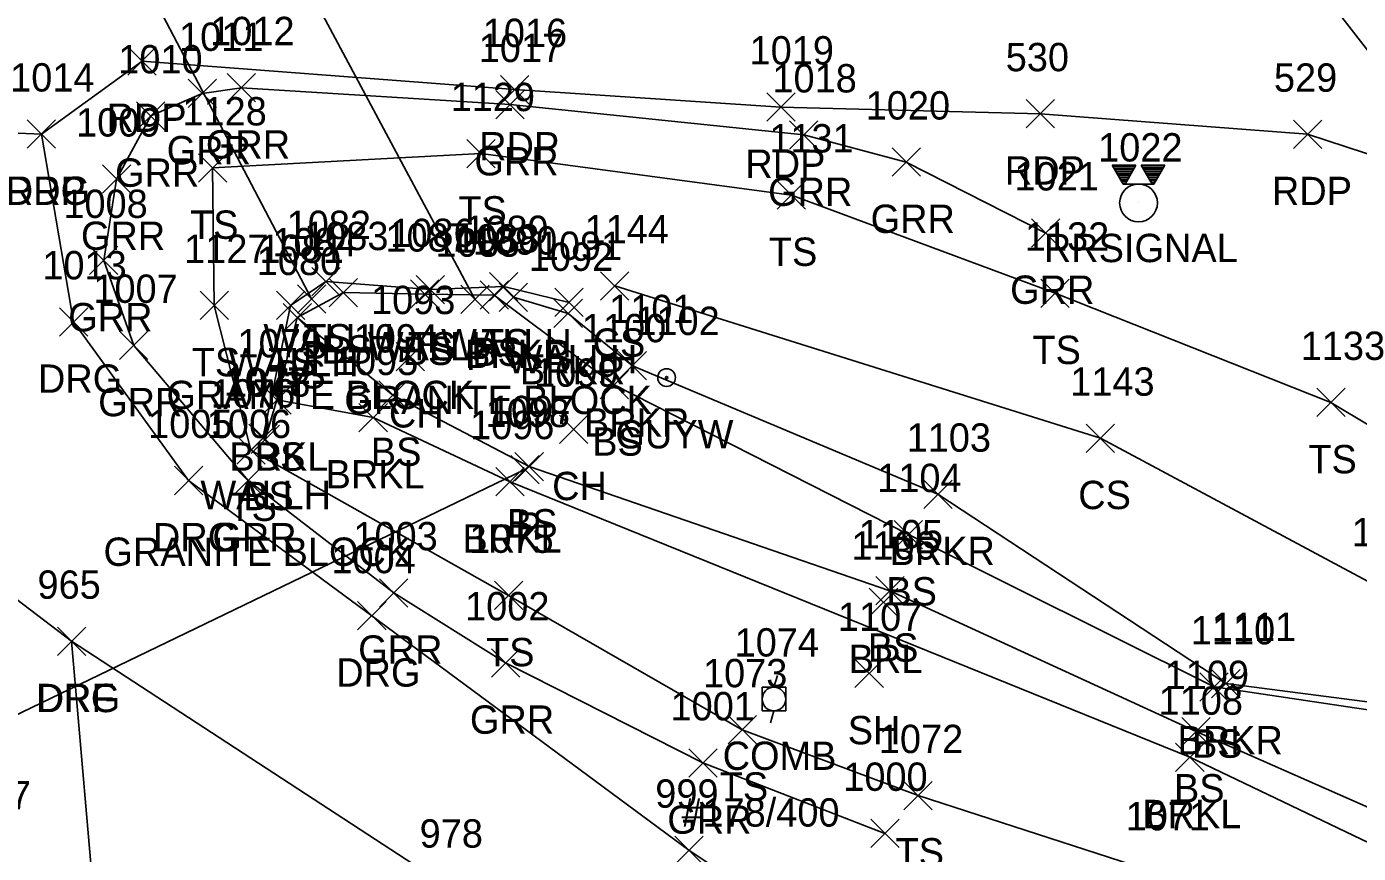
# Model space of a CAD drawing. Extents: x 1679360 to 1685861, y 903420 to 905946.
# Drawn here: x 1679736.4 to 1679830.3, y 903963.9 to 904022.2 of the extents above; entities that cross this region are included whole.
import ezdxf

# ---------------------------------------------------------------- set-up
doc = ezdxf.new("R2010")
doc.units = 0
for name, color, linetype in [('D_A', 7, 'Continuous'), ('D_C', 7, 'Continuous'), ('D_I', 7, 'Continuous'), ('D_TIC', 7, 'Continuous'), ('DCP', 7, 'Continuous'), ('DHW', 7, 'Continuous'), ('L_A', 7, 'Continuous'), ('L_I', 7, 'Continuous'), ('L_TIC', 7, 'Continuous'), ('LAWE', 7, 'Continuous'), ('LELB', 7, 'Continuous'), ('P_A', 7, 'Continuous'), ('P_I', 7, 'Continuous'), ('P_TIC', 7, 'Continuous'), ('PET', 7, 'Continuous'), ('R_A', 7, 'Continuous'), ('R_I', 7, 'Continuous'), ('R_TIC', 7, 'Continuous'), ('RDF', 7, 'Continuous'), ('RDG', 7, 'Continuous'), ('RGR', 7, 'Continuous'), ('RR', 7, 'Continuous'), ('TCSH', 7, 'Continuous'), ('U_A', 7, 'Continuous'), ('U_C', 7, 'Continuous'), ('U_I', 7, 'Continuous'), ('UP', 7, 'Continuous'), ('UPGW', 7, 'Continuous')]:
    doc.layers.add(name, color=color, linetype=linetype)

msp = doc.modelspace()

# ---------------------------------------------------------------- linework, layer by layer
at = {"layer": 'D_TIC'}
for points in [[(1679756.54, 904003.217), (1679758.54, 904005.217)], [(1679758.54, 904003.217), (1679756.54, 904005.217)], [(1679769.077, 904002.866), (1679771.077, 904004.866)], [(1679771.077, 904002.866), (1679769.077, 904004.866)], [(1679755.528, 904001.994), (1679757.528, 904003.994)], [(1679757.528, 904001.994), (1679755.528, 904003.994)], [(1679763.901, 904002.649), (1679765.901, 904004.649)], [(1679765.901, 904002.649), (1679763.901, 904004.649)], [(1679767.043, 904001.965), (1679769.043, 904003.965)], [(1679769.043, 904001.965), (1679767.043, 904003.965)], [(1679754.05, 904001.532), (1679756.05, 904003.532)], [(1679756.05, 904001.532), (1679754.05, 904003.532)], [(1679773.691, 904001.741), (1679775.691, 904003.741)], [(1679775.691, 904001.741), (1679773.691, 904003.741)], [(1679752.098, 903992.157), (1679754.098, 903994.157)], [(1679754.098, 903992.157), (1679752.098, 903994.157)], [(1679770.568, 903989.946), (1679772.568, 903991.946)], [(1679772.568, 903989.946), (1679770.568, 903991.946)]]:
    msp.add_lwpolyline(points, dxfattribs=at)
at = {"layer": 'DCP'}
for points in [[(1679722.806, 904067.249), (1679756.528, 904002.994)], [(1679733.684, 904067.194), (1679768.043, 904002.965)], [(1679729.232, 903970.53), (1679771.568, 903990.946)]]:
    msp.add_lwpolyline(points, dxfattribs=at)
at = {"layer": 'DHW'}
for points in [[(1679757.54, 904004.217), (1679764.901, 904003.649)], [(1679770.077, 904003.866), (1679774.691, 904002.741)], [(1679753.098, 903993.157), (1679755.05, 904002.532)]]:
    msp.add_lwpolyline(points, dxfattribs=at)
at = {"layer": 'L_TIC'}
for points in [[(1679767.469, 904012.239), (1679769.469, 904014.239)], [(1679769.469, 904012.239), (1679767.469, 904014.239)], [(1679748.546, 904011.229), (1679750.546, 904013.229)], [(1679750.546, 904011.229), (1679748.546, 904013.229)], [(1679789.366, 904009.321), (1679791.366, 904011.321)], [(1679791.366, 904009.321), (1679789.366, 904011.321)], [(1679756.54, 904003.217), (1679758.54, 904005.217)], [(1679758.54, 904003.217), (1679756.54, 904005.217)], [(1679769.077, 904002.866), (1679771.077, 904004.866)], [(1679771.077, 904002.866), (1679769.077, 904004.866)], [(1679776.904, 904002.912), (1679778.904, 904004.912)], [(1679778.904, 904002.912), (1679776.904, 904004.912)], [(1679757.772, 904002.433), (1679759.772, 904004.433)], [(1679759.772, 904002.433), (1679757.772, 904004.433)], [(1679763.509, 904002.328), (1679765.509, 904004.328)], [(1679765.509, 904002.328), (1679763.509, 904004.328)], [(1679763.901, 904002.649), (1679765.901, 904004.649)], [(1679765.901, 904002.649), (1679763.901, 904004.649)], [(1679768.411, 904002.26), (1679770.411, 904004.26)], [(1679770.411, 904002.26), (1679768.411, 904004.26)], [(1679769.758, 904002.113), (1679771.758, 904004.113)], [(1679771.758, 904002.113), (1679769.758, 904004.113)], [(1679807.954, 904002.393), (1679809.954, 904004.393)], [(1679809.954, 904002.393), (1679807.954, 904004.393)], [(1679748.667, 904001.531), (1679750.667, 904003.531)], [(1679750.667, 904001.531), (1679748.667, 904003.531)], [(1679754.05, 904001.532), (1679756.05, 904003.532)], [(1679756.05, 904001.532), (1679754.05, 904003.532)], [(1679773.622, 904000.969), (1679775.622, 904002.969)], [(1679775.622, 904000.969), (1679773.622, 904002.969)], [(1679754.517, 904000.673), (1679756.517, 904002.673)], [(1679756.517, 904000.673), (1679754.517, 904002.673)], [(1679754.517, 904000.673), (1679756.517, 904002.673)], [(1679756.517, 904000.673), (1679754.517, 904002.673)], [(1679762.491, 903997.919), (1679764.491, 903999.919)], [(1679764.491, 903997.919), (1679762.491, 903999.919)], [(1679778.149, 903997.281), (1679780.149, 903999.281)], [(1679780.149, 903997.281), (1679778.149, 903999.281)], [(1679776.875, 903995.933), (1679778.875, 903997.933)], [(1679778.875, 903995.933), (1679776.875, 903997.933)], [(1679753.084, 903994.867), (1679755.084, 903996.867)], [(1679755.084, 903994.867), (1679753.084, 903996.867)], [(1679753.084, 903994.867), (1679755.084, 903996.867)], [(1679755.084, 903994.867), (1679753.084, 903996.867)], [(1679761.265, 903995.209), (1679763.265, 903997.209)], [(1679763.265, 903995.209), (1679761.265, 903997.209)], [(1679827.407, 903994.686), (1679829.407, 903996.686)], [(1679829.407, 903994.686), (1679827.407, 903996.686)], [(1679759.871, 903993.62), (1679761.871, 903995.62)], [(1679761.871, 903993.62), (1679759.871, 903995.62)], [(1679774.004, 903992.793), (1679776.004, 903994.793)], [(1679776.004, 903992.793), (1679774.004, 903994.793)], [(1679752.265, 903992.087), (1679754.265, 903994.087)], [(1679754.265, 903992.087), (1679752.265, 903994.087)], [(1679811.152, 903992.161), (1679813.152, 903994.161)], [(1679813.152, 903992.161), (1679811.152, 903994.161)], [(1679751.253, 903991.328), (1679753.253, 903993.328)], [(1679753.253, 903991.328), (1679751.253, 903993.328)], [(1679770.871, 903990.159), (1679772.871, 903992.159)], [(1679772.871, 903990.159), (1679770.871, 903992.159)], [(1679769.523, 903989.096), (1679771.523, 903991.096)], [(1679771.523, 903989.096), (1679769.523, 903991.096)], [(1679799.693, 903988.211), (1679801.693, 903990.211)], [(1679801.693, 903988.211), (1679799.693, 903990.211)], [(1679797.619, 903985.362), (1679799.619, 903987.362)], [(1679799.619, 903985.362), (1679797.619, 903987.362)], [(1679796.314, 903981.397), (1679798.314, 903983.397)], [(1679798.314, 903981.397), (1679796.314, 903983.397)], [(1679769.418, 903981.075), (1679771.418, 903983.075)], [(1679771.418, 903981.075), (1679769.418, 903983.075)], [(1679795.86, 903980.596), (1679797.86, 903982.596)], [(1679797.86, 903980.596), (1679795.86, 903982.596)], [(1679794.849, 903975.571), (1679796.849, 903977.571)], [(1679796.849, 903975.571), (1679794.849, 903977.571)], [(1679820, 903974.857), (1679822, 903976.857)], [(1679822, 903974.857), (1679820, 903976.857)], [(1679819.173, 903974.618), (1679821.173, 903976.618)], [(1679821.173, 903974.618), (1679819.173, 903976.618)], [(1679785.9, 903971.592), (1679787.9, 903973.592)], [(1679787.9, 903971.592), (1679785.9, 903973.592)], [(1679817.901, 903971.468), (1679819.901, 903973.468)], [(1679819.901, 903971.468), (1679817.901, 903973.468)], [(1679817.461, 903969.652), (1679819.461, 903971.652)], [(1679819.461, 903969.652), (1679817.461, 903971.652)], [(1679798.3, 903966.949), (1679800.3, 903968.949)], [(1679800.3, 903966.949), (1679798.3, 903968.949)]]:
    msp.add_lwpolyline(points, dxfattribs=at)
at = {"layer": 'LAWE'}
for points in [[(1679770.758, 904003.113), (1679774.622, 904001.969), (1679779.149, 903998.281), (1679800.693, 903989.211), (1679821, 903975.857), (1679836.965, 903973.787), (1679846.91, 903974.341), (1679851.31, 903976.645)], [(1679754.084, 903995.867), (1679760.871, 903994.62), (1679770.523, 903990.096), (1679818.461, 903970.652), (1679836.034, 903962.252), (1679850.756, 903964.941), (1679856.581, 903970.528)]]:
    msp.add_lwpolyline(points, dxfattribs=at)
at = {"layer": 'LELB'}
for points in [[(1679826.909, 903946.775), (1679816.139, 903962.498), (1679799.3, 903967.949), (1679786.9, 903972.592), (1679770.418, 903982.075), (1679752.253, 903992.328), (1679749.667, 904002.531), (1679749.546, 904012.229), (1679768.469, 904013.239), (1679790.366, 904010.321), (1679808.954, 904003.393), (1679828.407, 903995.686), (1679842.28, 903987.378), (1679854.89, 903981.602), (1679861.766, 903973.84), (1679868.316, 903960.054)], [(1679755.05, 904002.532), (1679757.54, 904004.217)], [(1679846.701, 903976.921), (1679832.005, 903982.539), (1679812.152, 903993.161), (1679777.904, 904003.912)], [(1679753.265, 903993.087), (1679754.084, 903995.867), (1679755.517, 904001.673), (1679758.772, 904003.433), (1679764.509, 904003.328), (1679769.411, 904003.26), (1679777.875, 903996.933), (1679798.619, 903986.362), (1679820.173, 903975.618), (1679837.139, 903973.094), (1679847.38, 903972.765), (1679851.382, 903976.558)], [(1679764.901, 904003.649), (1679770.077, 904003.866)], [(1679755.517, 904001.673), (1679762.265, 903996.209), (1679771.871, 903991.159), (1679797.314, 903982.397), (1679818.901, 903972.468), (1679836.645, 903964.65), (1679849.36, 903967.246), (1679856.205, 903970.751)]]:
    msp.add_lwpolyline(points, dxfattribs=at)
at = {"layer": 'P_TIC'}
for points in [[(1679743.579, 904018.774), (1679745.579, 904020.774)], [(1679745.579, 904018.774), (1679743.579, 904020.774)], [(1679769.859, 904016.762), (1679771.859, 904018.762)], [(1679771.859, 904016.762), (1679769.859, 904018.762)], [(1679788.628, 904015.53), (1679790.628, 904017.53)], [(1679790.628, 904015.53), (1679788.628, 904017.53)], [(1679788.628, 904015.53), (1679790.628, 904017.53)], [(1679790.628, 904015.53), (1679788.628, 904017.53)], [(1679806.928, 904015.053), (1679808.928, 904017.053)], [(1679808.928, 904015.053), (1679806.928, 904017.053)], [(1679736.475, 904013.621), (1679738.475, 904015.621)], [(1679738.475, 904013.621), (1679736.475, 904015.621)], [(1679825.762, 904013.608), (1679827.762, 904015.608)], [(1679827.762, 904013.608), (1679825.762, 904015.608)]]:
    msp.add_lwpolyline(points, dxfattribs=at)
at = {"layer": 'PET'}
for points in [[(1679464.445, 904041.772), (1679494.847, 904039.777), (1679533.658, 904036.864), (1679564.761, 904034.751), (1679595.94, 904030.795), (1679627.793, 904028.133), (1679661.16, 904024.917), (1679697.205, 904019.689), (1679719.417, 904015.397), (1679737.475, 904014.621), (1679744.579, 904019.774), (1679770.859, 904017.762), (1679789.628, 904016.53)], [(1680207.925, 903985.129), (1680151.693, 903989.51), (1680097.956, 903992.814), (1680047.952, 903996.664), (1679996.841, 904001.699), (1679939.177, 904006.29), (1679891.591, 904009.092), (1679852.589, 904011.923), (1679848.664, 904011.26), (1679842.11, 904010.48), (1679836.311, 904011.491), (1679826.762, 904014.608), (1679807.928, 904016.053), (1679789.628, 904016.53)]]:
    msp.add_lwpolyline(points, dxfattribs=at)
at = {"layer": 'R_TIC'}
for points in [[(1679747.822, 904016.487), (1679749.822, 904018.487)], [(1679749.822, 904016.487), (1679747.822, 904018.487)], [(1679750.584, 904016.893), (1679752.584, 904018.893)], [(1679752.584, 904016.893), (1679750.584, 904018.893)], [(1679769.522, 904015.702), (1679771.522, 904017.702)], [(1679771.522, 904015.702), (1679769.522, 904017.702)], [(1679744.181, 904014.902), (1679746.181, 904016.902)], [(1679746.181, 904014.902), (1679744.181, 904016.902)], [(1679736.475, 904013.621), (1679738.475, 904015.621)], [(1679738.475, 904013.621), (1679736.475, 904015.621)], [(1679790.232, 904013.556), (1679792.232, 904015.556)], [(1679792.232, 904013.556), (1679790.232, 904015.556)], [(1679797.462, 904011.646), (1679799.462, 904013.646)], [(1679799.462, 904011.646), (1679797.462, 904013.646)], [(1679741.775, 904010.445), (1679743.775, 904012.445)], [(1679743.775, 904010.445), (1679741.775, 904012.445)], [(1679807.299, 904006.641), (1679809.299, 904008.641)], [(1679809.299, 904006.641), (1679807.299, 904008.641)], [(1679740.875, 904004.703), (1679742.875, 904006.703)], [(1679742.875, 904004.703), (1679740.875, 904006.703)], [(1679738.743, 904000.37), (1679740.743, 904002.37)], [(1679740.743, 904000.37), (1679738.743, 904002.37)], [(1679742.99, 903998.712), (1679744.99, 904000.712)], [(1679744.99, 903998.712), (1679742.99, 904000.712)], [(1679746.854, 903989.18), (1679748.854, 903991.18)], [(1679748.854, 903989.18), (1679746.854, 903991.18)], [(1679751.045, 903989.179), (1679753.045, 903991.179)], [(1679753.045, 903989.179), (1679751.045, 903991.179)], [(1679761.326, 903981.253), (1679763.326, 903983.253)], [(1679763.326, 903981.253), (1679761.326, 903983.253)], [(1679759.777, 903979.639), (1679761.777, 903981.639)], [(1679761.777, 903979.639), (1679759.777, 903981.639)], [(1679738.608, 903977.837), (1679740.608, 903979.837)], [(1679740.608, 903977.837), (1679738.608, 903979.837)], [(1679738.608, 903977.837), (1679740.608, 903979.837)], [(1679740.608, 903977.837), (1679738.608, 903979.837)], [(1679769.205, 903976.312), (1679771.205, 903978.312)], [(1679771.205, 903976.312), (1679769.205, 903978.312)], [(1679783.124, 903969.258), (1679785.124, 903971.258)], [(1679785.124, 903969.258), (1679783.124, 903971.258)], [(1679795.959, 903964.284), (1679797.959, 903966.284)], [(1679797.959, 903964.284), (1679795.959, 903966.284)], [(1679782.134, 903963.096), (1679784.134, 903965.096)], [(1679784.134, 903963.096), (1679782.134, 903965.096)]]:
    msp.add_lwpolyline(points, dxfattribs=at)
at = {"layer": 'RDF'}
msp.add_lwpolyline([(1679739.608, 903978.837), (1679741.406, 903958.01), (1679740.349, 903940.875)], dxfattribs=at)
at = {"layer": 'RDG'}
for points in [[(1679661.16, 904024.917), (1679683.887, 904015.944), (1679697.931, 904008.669), (1679719.81, 903993.908), (1679739.608, 903978.837), (1679766.509, 903961.278), (1679785.717, 903950.364), (1679809.974, 903931.781)], [(1679817.493, 903938.584), (1679800, 903952.789), (1679783.134, 903964.096), (1679760.777, 903980.639), (1679747.854, 903990.18), (1679739.743, 904001.37), (1679737.475, 904014.621)]]:
    msp.add_lwpolyline(points, dxfattribs=at)
at = {"layer": 'RGR'}
msp.add_lwpolyline([(1679796.959, 903965.284), (1679784.124, 903970.258), (1679770.205, 903977.312), (1679762.326, 903982.253), (1679752.045, 903990.179), (1679743.99, 903999.712), (1679741.875, 904005.703), (1679742.775, 904011.445), (1679745.181, 904015.902), (1679748.822, 904017.487), (1679751.584, 904017.893), (1679770.522, 904016.702), (1679791.232, 904014.556), (1679798.462, 904012.646), (1679808.299, 904007.641)], dxfattribs=at)
at = {"layer": 'RR'}
msp.add_lwpolyline([(1679824.636, 904028.723), (1679837.335, 904012.385), (1679861.93, 903982.575), (1679878.201, 903963.702), (1679892.43, 903947.813), (1679907.949, 903930.191), (1679922.381, 903914.406), (1679937.847, 903897.677), (1679952.054, 903882.523), (1679968.97, 903864.985), (1679984.514, 903848.778), (1680002.835, 903830.071), (1680018.619, 903814.033), (1680033.052, 903799.461), (1680047.501, 903784.671), (1680062.832, 903769.48), (1680079.575, 903752.46), (1680095.318, 903736.478)], dxfattribs=at)
at = {"layer": 'TCSH'}
for p, q in [((1679814.66, 904012.43), (1679812.993, 904012.43)), ((1679812.993, 904012.43), (1679813.763, 904011.096)), ((1679813.89, 904011.096), (1679814.66, 904012.43)), ((1679816.695, 904012.43), (1679815.028, 904012.43)), ((1679815.028, 904012.43), (1679815.798, 904011.096)), ((1679815.925, 904011.096), (1679816.695, 904012.43)), ((1679815.925, 904011.096), (1679813.763, 904011.096)), ((1679814.844, 904009.763), (1679814.844, 904009.763))]:
    msp.add_line(p, q, dxfattribs=at)
for points in [[(1679813.038, 904012.353), (1679814.616, 904012.353)], [(1679815.056, 904012.382), (1679816.667, 904012.382)], [(1679813.115, 904012.22), (1679814.539, 904012.22)], [(1679813.191, 904012.087), (1679814.462, 904012.087)], [(1679813.268, 904011.953), (1679814.385, 904011.953)], [(1679813.345, 904011.82), (1679814.308, 904011.82)], [(1679813.422, 904011.687), (1679814.231, 904011.687)], [(1679813.499, 904011.553), (1679814.154, 904011.553)], [(1679813.576, 904011.42), (1679814.077, 904011.42)], [(1679815.133, 904012.248), (1679816.59, 904012.248)], [(1679815.21, 904012.115), (1679816.513, 904012.115)], [(1679815.287, 904011.982), (1679816.436, 904011.982)], [(1679815.364, 904011.848), (1679816.359, 904011.848)], [(1679815.441, 904011.715), (1679816.282, 904011.715)], [(1679815.518, 904011.582), (1679816.205, 904011.582)], [(1679815.595, 904011.448), (1679816.128, 904011.448)], [(1679813.653, 904011.287), (1679814, 904011.287)], [(1679813.73, 904011.153), (1679813.923, 904011.153)], [(1679815.672, 904011.315), (1679816.051, 904011.315)], [(1679815.749, 904011.182), (1679815.974, 904011.182)]]:
    msp.add_lwpolyline(points, dxfattribs=at)
msp.add_circle((1679814.844, 904009.763), 1.333, dxfattribs=at)
at = {"layer": 'UP'}
for p, q in [((1679789.381, 903976.427), (1679789.131, 903975.594)), ((1679788.298, 903973.927), (1679788.298, 903975.594)), ((1679788.298, 903975.594), (1679789.964, 903975.594)), ((1679789.131, 903974.761), (1679789.131, 903974.761)), ((1679789.964, 903975.594), (1679789.964, 903973.927)), ((1679789.964, 903973.927), (1679788.298, 903973.927)), ((1679788.881, 903973.094), (1679789.131, 903973.927))]:
    msp.add_line(p, q, dxfattribs=at)
msp.add_circle((1679789.131, 903974.761), 0.833, dxfattribs=at)
at = {"layer": 'UPGW'}
for radius in [0.625, 0.0833]:
    msp.add_circle((1679781.563, 903997.443), radius, dxfattribs=at)

# ---------------------------------------------------------------- texts
at = {"layer": 'D_A'}
for s, p in [('WALLH', (1679753.131, 903999.217)), ('WALLH', (1679760.491, 903998.649)), ('WALLH', (1679765.668, 903998.866)), ('WALLH', (1679750.641, 903997.532)), ('P', (1679755.906, 903997.994)), ('P', (1679767.421, 903997.965)), ('WALLH', (1679770.281, 903997.741)), ('WALLH', (1679748.689, 903988.157)), ('P', (1679770.946, 903985.946))]:
    msp.add_text(s, height=2, dxfattribs=at).set_placement(p)
at = {"layer": 'D_C'}
for p in [(1679746.296, 903995.217), (1679758.833, 903994.866), (1679741.854, 903984.157)]:
    msp.add_text('GRANITE BLOCK', height=2, dxfattribs=at).set_placement(p)
at = {"layer": 'D_I'}
for s, p in [('1082', (1679754.768, 904007.217)), ('1086', (1679762.074, 904006.649)), ('1089', (1679767.298, 904006.866)), ('1084', (1679753.757, 904005.994)), ('1085', (1679765.271, 904005.965)), ('1091', (1679772.486, 904005.741)), ('1081', (1679752.846, 904005.532)), ('1077', (1679750.326, 903996.157)), ('1098', (1679768.796, 903993.946))]:
    msp.add_text(s, height=2, dxfattribs=at).set_placement(p)
at = {"layer": 'L_A'}
for s, p in [('TS', (1679766.878, 904008.239)), ('TS', (1679747.955, 904007.229)), ('TS', (1679788.775, 904005.321)), ('TS', (1679755.95, 903999.217)), ('BS', (1679757.213, 903998.433)), ('BS', (1679762.95, 903998.328)), ('TS', (1679763.31, 903998.649)), ('BRKR', (1679767.349, 903998.113)), ('BS', (1679767.852, 903998.26)), ('TS', (1679768.487, 903998.866)), ('CS', (1679776.345, 903998.912)), ('TS', (1679807.363, 903998.393)), ('TS', (1679748.076, 903997.531)), ('TS', (1679753.46, 903997.532)), ('BS', (1679753.958, 903996.673)), ('BS', (1679753.958, 903996.673)), ('BRKR', (1679771.212, 903996.969)), ('CH', (1679761.979, 903993.919)), ('BRKR', (1679775.74, 903993.281)), ('BS', (1679776.316, 903991.933)), ('BRKL', (1679750.729, 903990.867)), ('BS', (1679752.525, 903990.867)), ('BS', (1679760.706, 903991.209)), ('TS', (1679826.817, 903990.686)), ('BRKL', (1679757.517, 903989.62)), ('CH', (1679773.492, 903988.793)), ('BS', (1679751.706, 903988.087)), ('CS', (1679810.593, 903988.161)), ('TS', (1679750.663, 903987.328)), ('BS', (1679770.312, 903986.159)), ('BRKL', (1679767.169, 903985.096)), ('BRKR', (1679797.284, 903984.211)), ('BS', (1679797.06, 903981.362)), ('TS', (1679768.827, 903977.075)), ('BRL', (1679794.403, 903976.596)), ('BS', (1679795.755, 903977.397)), ('SH', (1679794.338, 903971.571)), ('BRKR', (1679817.591, 903970.857)), ('BS', (1679818.614, 903970.618)), ('TS', (1679785.31, 903967.592)), ('BS', (1679817.342, 903967.468)), ('BRKL', (1679815.107, 903965.652)), ('TS', (1679797.709, 903962.949))]:
    msp.add_text(s, height=2, dxfattribs=at).set_placement(p)
at = {"layer": 'L_I'}
for s, p in [('1129', (1679766.335, 904016.239)), ('1128', (1679747.42, 904015.229)), ('1131', (1679788.807, 904013.321)), ('1082', (1679754.768, 904007.217)), ('1086', (1679762.074, 904006.649)), ('1089', (1679767.298, 904006.866)), ('1144', (1679775.778, 904006.912)), ('1083', (1679756.001, 904006.433)), ('1087', (1679761.737, 904006.328)), ('1088', (1679766.639, 904006.26)), ('1090', (1679767.9, 904006.113)), ('1132', (1679806.828, 904006.393)), ('1127', (1679747.541, 904005.531)), ('1080', (1679752.659, 904004.673)), ('1080', (1679752.659, 904004.673)), ('1081', (1679752.846, 904005.532)), ('1092', (1679771.85, 904004.969)), ('1093', (1679760.719, 904001.919)), ('1101', (1679777.511, 904001.281)), ('1094', (1679759.493, 903999.209)), ('1100', (1679775.584, 903999.933)), ('1079', (1679751.304, 903998.867)), ('1079', (1679751.304, 903998.867)), ('1133', (1679826.281, 903998.686)), ('1095', (1679758.099, 903997.62)), ('1099', (1679772.224, 903996.793)), ('1076', (1679749.426, 903995.328)), ('1078', (1679750.493, 903996.087)), ('1143', (1679810.026, 903996.161)), ('1097', (1679769.099, 903994.159)), ('1096', (1679767.696, 903993.096)), ('1103', (1679798.489, 903992.211)), ('1104', (1679796.415, 903989.362)), ('1075', (1679767.646, 903985.075)), ('1105', (1679795.109, 903985.397)), ('1142', (1679829.879, 903985.539)), ('1106', (1679794.6, 903984.596)), ('1107', (1679793.645, 903979.571)), ('1110', (1679818.528, 903978.618)), ('1111', (1679820.008, 903978.857)), ('1073', (1679784.129, 903975.592)), ('1109', (1679816.688, 903975.468)), ('1108', (1679816.257, 903973.652)), ('1072', (1679796.528, 903970.949)), ('967', (1679732.278, 903966.979)), ('1071', (1679813.934, 903965.498))]:
    msp.add_text(s, height=2, dxfattribs=at).set_placement(p)
at = {"layer": 'P_A'}
for p in [(1679742.067, 904014.774), (1679768.347, 904012.762), (1679787.116, 904011.53), (1679787.116, 904011.53), (1679805.416, 904011.053), (1679734.963, 904009.621), (1679824.25, 904009.608)]:
    msp.add_text('RDP', height=2, dxfattribs=at).set_placement(p)
at = {"layer": 'P_I'}
for s, p in [('1016', (1679768.599, 904020.762)), ('1019', (1679787.415, 904019.53)), ('1019', (1679787.415, 904019.53)), ('530', (1679805.479, 904019.053)), ('1014', (1679735.271, 904017.621)), ('529', (1679824.392, 904017.608))]:
    msp.add_text(s, height=2, dxfattribs=at).set_placement(p)
at = {"layer": 'R_A'}
for s, p in [('GRR', (1679746.31, 904012.487)), ('GRR', (1679749.072, 904012.893)), ('GRR', (1679768.01, 904011.702)), ('GRR', (1679742.669, 904010.902)), ('DRG', (1679734.963, 904009.621)), ('GRR', (1679788.721, 904009.556)), ('GRR', (1679795.95, 904007.646)), ('GRR', (1679740.263, 904006.445)), ('RRSIGNAL', (1679808.17, 904005.585)), ('GRR', (1679805.788, 904002.641)), ('GRR', (1679739.363, 904000.703)), ('DRG', (1679737.231, 903996.37)), ('GRR', (1679741.478, 903994.712)), ('DRG', (1679745.342, 903985.18)), ('GRR', (1679749.533, 903985.179)), ('GRR', (1679759.814, 903977.253)), ('DRG', (1679758.265, 903975.639)), ('DRG', (1679737.097, 903973.837)), ('DRF', (1679737.144, 903973.837)), ('GRR', (1679767.693, 903972.312)), ('GRR', (1679781.612, 903965.258))]:
    msp.add_text(s, height=2, dxfattribs=at).set_placement(p)
at = {"layer": 'R_I'}
for s, p in [('1012', (1679749.379, 904020.893)), ('1011', (1679747.184, 904020.487)), ('1017', (1679768.317, 904019.702)), ('1010', (1679742.89, 904018.902)), ('1014', (1679735.271, 904017.621)), ('1018', (1679789.028, 904017.556)), ('1020', (1679795.604, 904015.646)), ('1009', (1679739.916, 904014.445)), ('1022', (1679811.997, 904012.685)), ('1021', (1679806.095, 904010.641)), ('1008', (1679739.025, 904008.703)), ('1013', (1679737.539, 904004.37)), ('1007', (1679741.139, 904002.712)), ('1005', (1679745.003, 903993.18)), ('1006', (1679749.139, 903993.179)), ('1003', (1679759.476, 903985.253)), ('1004', (1679757.927, 903983.639)), ('965', (1679737.199, 903981.837)), ('965', (1679737.199, 903981.837)), ('1002', (1679767.355, 903980.312)), ('1001', (1679781.84, 903973.258)), ('1000', (1679794.022, 903968.284)), ('999', (1679780.764, 903967.096)), ('978', (1679764.147, 903964.278)), ('978', (1679764.147, 903964.278))]:
    msp.add_text(s, height=2, dxfattribs=at).set_placement(p)
at = {"layer": 'U_A'}
for s, p in [('GUYW', (1679777.956, 903992.443)), ('COMB', (1679785.517, 903969.761))]:
    msp.add_text(s, height=2, dxfattribs=at).set_placement(p)
at = {"layer": 'U_C'}
msp.add_text('#178/400', height=2, dxfattribs=at).set_placement((1679782.604, 903965.761))
at = {"layer": 'U_I'}
for s, p in [('1102', (1679779.358, 904000.443)), ('1074', (1679786.359, 903977.761))]:
    msp.add_text(s, height=2, dxfattribs=at).set_placement(p)

doc.saveas('drawing.dxf')
